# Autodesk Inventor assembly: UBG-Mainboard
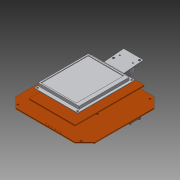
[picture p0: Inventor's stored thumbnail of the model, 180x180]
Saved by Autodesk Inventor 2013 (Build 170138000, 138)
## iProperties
Created: 2012-08
Part Number: UBG-Mainboard
Document SubType Name: Assembly
Designer: rYan
Mass: 98.2021 g
Surface Area: 652.595 cm^2
Volume: 62.0501 cm^3
Density: 1.58263 g/cm^3
Author: rYan
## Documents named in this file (6)
- D:\SVN\2013\Inventor\Elektronik\UBG-Mainboard.iam
- D:\SVN\2013\Inventor\Elektronik\Mainboard.ipt
- D:\SVN\2013\Inventor\Kaufteile\Molex 52207-1160.ipt
- D:\SVN\2013\Inventor\Elektronik\Extension Board.ipt
- D:\SVN\2013\Inventor\Elektronik\TFT Display.ipt
- D:\SVN\2013\Inventor\Elektronik\MG-Kamera.iam
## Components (8 placed, 5 different names)
1. Mainboard:1 — Passend:1, Fluchtend:1, Passend:2, Fluchtend:2, Passend:3, Passend:4, Fluchtend:3, Fluchtend:4, Fluchtend:5, Fluchtend:7, Fluchtend:9, Fluchtend:10, Passend:5
2. Molex 52207-1160:1 — Passend:1, Fluchtend:1, Fluchtend:5, Fluchtend:6
3. Molex 52207-1160:3 — Passend:3, Fluchtend:4, Fluchtend:6
4. Molex 52207-1160:2 — Passend:2, Fluchtend:2, Fluchtend:7, Fluchtend:8
5. Molex 52207-1160:4 — Passend:4, Fluchtend:3, Fluchtend:8
6. Extension Board:1 — Fluchtend:9, Fluchtend:10, Passend:5, Passend:6, Fluchtend:11, Winkel:7, Passend:13, Passend:14, Fluchtend:12
7. TFT Display:1 — Passend:6, Fluchtend:11
8. MG-Kamera:1 [sub-assembly] — Winkel:7, Passend:13, Passend:14, Fluchtend:12
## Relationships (21: Flush 12, Mate 8, Angle 1)
- Passend:1 [Mate]: Mainboard:1 ↔ Molex 52207-1160:1
- Fluchtend:1 [Flush]: Mainboard:1 ↔ Molex 52207-1160:1
- Passend:2 [Mate]: Mainboard:1 ↔ Molex 52207-1160:2
- Fluchtend:2 [Flush]: Mainboard:1 ↔ Molex 52207-1160:2
- Passend:3 [Mate]: Mainboard:1 ↔ Molex 52207-1160:3
- Passend:4 [Mate]: Mainboard:1 ↔ Molex 52207-1160:4
- Fluchtend:3 [Flush]: Mainboard:1 ↔ Molex 52207-1160:4
- Fluchtend:4 [Flush]: Mainboard:1 ↔ Molex 52207-1160:3
- Fluchtend:5 [Flush]: Mainboard:1 ↔ Molex 52207-1160:1
- Fluchtend:6 [Flush]: Molex 52207-1160:1 ↔ Molex 52207-1160:3
- Fluchtend:7 [Flush]: Mainboard:1 ↔ Molex 52207-1160:2
- Fluchtend:8 [Flush]: Molex 52207-1160:2 ↔ Molex 52207-1160:4
- Fluchtend:9 [Flush]: Mainboard:1 ↔ Extension Board:1
- Fluchtend:10 [Flush]: Mainboard:1 ↔ Extension Board:1
- Passend:5 [Mate]: Mainboard:1 ↔ Extension Board:1
- Passend:6 [Mate]: Extension Board:1 ↔ TFT Display:1
- Fluchtend:11 [Flush]: Extension Board:1 ↔ TFT Display:1
- Winkel:7 [Angle]: Extension Board:1 ↔ MG-Kamera:1
- Passend:13 [Mate]: Extension Board:1 ↔ MG-Kamera:1
- Passend:14 [Mate]: Extension Board:1 ↔ MG-Kamera:1
- Fluchtend:12 [Flush]: Extension Board:1 ↔ MG-Kamera:1
